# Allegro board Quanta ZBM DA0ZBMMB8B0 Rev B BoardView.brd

Outline 198.2 x 89.4 mm; copper layers: TOP, SGND, IN1, IN2, IN3, IN4, IN5, BOTTOM. Coordinates in mm from the lower left corner of the outline.
Outline path: 0,79.66 0,69.3 arc(0.59,67.89) 2,67.3 2.05,67.3 arc(2.4,67.15) 2.55,66.8 2.55,64.15 3.15,63.55 8.85,63.55 arc(9.35,64.05) 9.85,63.55 9.85,50.05 arc(9.35,49.55) 8.85,50.05 3.55,50.05 2.95,49.45 2.95,48.25 arc(3.29,47.57) 2.7,47.1 2.2,47.1 arc(1.85,46.95) 1.7,46.6 1.7,45.65 2.3,45.05 12.41,45.05 arc(12.91,44.55) 12.41,44.05 12.41,38.5 arc(12.91,38) 12.41,37.5 1.85,37.5 1.25,36.9 1.25,35.1 2.7,35.1 arc(3.2,34.6) 2.7,34.1 1.25,34.1 1.25,18.6 arc(1.4,18.25) 1.75,18.1 3.75,18.1 arc(4.1,17.95) 4.25,17.6 4.25,15.3 arc(4.1,14.95) 3.75,14.8 1.75,14.8 arc(1.4,14.65) 1.25,14.3 1.25,2.4 arc(1.4,2.05) 1.75,1.9 2.35,1.9 arc(2.7,1.75) 2.85,1.4 2.85,1 arc(3.14,0.29) 3.85,0 7.35,0 arc(7.97,0.22) 8.32,0.79 9.56,6.46 arc(9.74,6.74) 10.05,6.85 21.45,6.85 arc(21.8,6.7) 21.95,6.35 21.95,6.1 arc(22.1,5.75) 22.45,5.6 78.2,5.6 arc(80.32,6.48) 81.2,8.6 arc(81.49,9.31) 82.2,9.6 197.2,9.6 arc(197.91,9.89) 198.2,10.6 198.2,88.4 arc(197.91,89.11) 197.2,89.4 79.17,89.4 arc(78.75,89.3) 78.4,89.03 68.42,76.87 arc(68.26,76.6) 68.2,76.29 arc(67.58,74.95) 66.2,74.4 36.7,74.4 arc(36.35,74.25) 36.2,73.9 arc(36.05,73.55) 35.7,73.4 18.8,73.4 18.8,73.6 arc(18.51,74.31) 17.8,74.6 14.8,74.6 arc(14.09,74.89) 13.8,75.6 13.8,76.66 arc(12.34,80.2) 8.8,81.66 2,81.66 arc(0.59,81.07) 0,79.66

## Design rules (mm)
constraint set DEFAULT: min track width 0.109
net group DFP-S3.5(3.2: nets M_A_DQS_0_DN M_A_DQS_0_DP M_A_DQS_1_DN M_A_DQS_1_DP M_A_DQS_2_DN M_A_DQS_2_DP M_A_DQS_3_DN M_A_DQS_3_DP M_A_LP4_CLK_DN M_A_LP4_CLK_DP M_B_DQS_0_DN M_B_DQS_0_DP M_B_DQS_1_DN M_B_DQS_1_DP M_B_DQS_2_DN M_B_DQS_2_DP M_B_DQS_3_DN M_B_DQS_3_DP M_B_LP4_CLK_DN M_B_LP4_CLK_DP M_C_DQS_0_DN M_C_DQS_0_DP M_C_DQS_1_DN M_C_DQS_1_DP M_C_DQS_2_DN M_C_DQS_2_DP M_C_DQS_3_DN M_C_DQS_3_DP M_C_LP4_CLK_DN M_C_LP4_CLK_DP M_D_DQS_0_DN M_D_DQS_0_DP M_D_DQS_1_DN M_D_DQS_1_DP M_D_DQS_2_DN M_D_DQS_2_DP M_D_DQS_3_DN M_D_DQS_3_DP M_D_LP4_CLK_DN M_D_LP4_CLK_DP
net group DFP-S3.5(4.2: nets CNV_CLK_PCH_RX_WLAN_TX_N CNV_CLK_PCH_RX_WLAN_TX_P CNV_CLK_PCH_TX_WLAN_RX_N CNV_CLK_PCH_TX_WLAN_RX_P CNV_D0_PCH_RX_WLAN_TX_N CNV_D0_PCH_RX_WLAN_TX_P CNV_D0_PCH_TX_WLAN_RX_N CNV_D0_PCH_TX_WLAN_RX_P CNV_D1_PCH_RX_WLAN_TX_N CNV_D1_PCH_RX_WLAN_TX_P CNV_D1_PCH_TX_WLAN_RX_N CNV_D1_PCH_TX_WLAN_RX_P EDP_AUX_C_N EDP_AUX_C_P EDP_AUX_N EDP_AUX_P EDP_TX0_C_N EDP_TX0_C_P EDP_TX0_N EDP_TX0_P EDP_TX1_C_N EDP_TX1_C_P EDP_TX1_N EDP_TX1_P EDP_TX2_C_N EDP_TX2_C_P EDP_TX2_N EDP_TX2_P EDP_TX3_C_N EDP_TX3_C_P EDP_TX3_N EDP_TX3_P H1_SBU1 H1_SBU2 N18155934 N18155937 N18182049 N18182083 PCIE_4_PCH_RX_WLAN_TX_C_N PCIE_4_PCH_RX_WLAN_TX_C_P PCIE_4_PCH_RX_WLAN_TX_N PCIE_4_PCH_RX_WLAN_TX_P PCIE_4_PCH_TX_WLAN_RX_C_N PCIE_4_PCH_TX_WLAN_RX_C_P PCIE_4_PCH_TX_WLAN_RX_N PCIE_4_PCH_TX_WLAN_RX_P PCIE_4_WLAN_REFCLK_N PCIE_4_WLAN_REFCLK_P PCIE_SUB_REFCLK_N PCIE_SUB_REFCLK_P USB2_BT_N USB2_BT_P USB2_UFC_N USB2_UFC_P USB_A0_SSRX_L_N USB_A0_SSRX_L_P USB_A0_SSRX_N USB_A0_SSRX_P USB_A0_SSTX_C_N USB_A0_SSTX_C_P USB_A0_SSTX_L_N USB_A0_SSTX_L_P USB_A0_SSTX_N USB_A0_SSTX_P USB_A0_USB2_L_N USB_A0_USB2_L_P USB_A0_USB2_N USB_A0_USB2_P USB_A0_USB2_U_N USB_A0_USB2_U_P USB_A1_SSRX_N USB_A1_SSRX_P USB_A1_SSTX_N USB_A1_SSTX_P USB_A1_USB2_N USB_A1_USB2_P USB_C0_AUX_DC_N USB_C0_AUX_DC_P USB_C0_AUX_N USB_C0_AUX_P USB_C0_ML0_N USB_C0_ML0_P USB_C0_ML1_N USB_C0_ML1_P USB_C0_ML2_N USB_C0_ML2_P USB_C0_ML3_N USB_C0_ML3_P USB_C0_RX1_C_N USB_C0_RX1_C_P USB_C0_RX1_L_N USB_C0_RX1_L_P USB_C0_RX1_U_N USB_C0_RX1_U_P USB_C0_RX2_C_N USB_C0_RX2_C_P USB_C0_RX2_L_N USB_C0_RX2_L_P USB_C0_RX2_U_N USB_C0_RX2_U_P USB_C0_SBU1_C USB_C0_SBU1_U USB_C0_SBU2_C USB_C0_SBU2_U USB_C0_SSRX_N USB_C0_SSRX_P USB_C0_SSTX_N USB_C0_SSTX_P USB_C0_TX1_C_N USB_C0_TX1_C_P USB_C0_TX1_L_N USB_C0_TX1_L_P USB_C0_TX1_U_N USB_C0_TX1_U_P USB_C0_TX2_C_N USB_C0_TX2_C_P USB_C0_TX2_L_N USB_C0_TX2_L_P USB_C0_TX2_U_N USB_C0_TX2_U_P USB_C0_USB2_L_N USB_C0_USB2_L_P USB_C0_USB2_N USB_C0_USB2_P USB_C0_USB2_U_N USB_C0_USB2_U_P USB_C1_AUX_N USB_C1_AUX_P USB_C1_ML0_N USB_C1_ML0_P USB_C1_ML1_N USB_C1_ML1_P USB_C1_ML2_N USB_C1_ML2_P USB_C1_ML3_N USB_C1_ML3_P USB_C1_SSRX_N USB_C1_SSRX_P USB_C1_SSTX_N USB_C1_SSTX_P USB_C1_USB2_N USB_C1_USB2_P
net group DFP-S4W4.3(3.8: nets PPVAR_VCC_IN_SNS_N PPVAR_VCC_IN_SNS_P VCCIN_AUX_SENSE_N VCCIN_AUX_SENSE_P
net group DFP-S7.2(6: nets HDMI_DDC_SCL HDMI_DDC_SDA USB_C1_AUX_N_HDMI_DDC_SDA USB_C1_AUX_P_HDMI_DDC_SCL
net group DFP-S7W4.3(3.8: nets AP_I2C_AUDIO_SCL AP_I2C_AUDIO_SDA AP_I2C_CAM_SCL AP_I2C_CAM_SDA AP_I2C_EMR_SCL AP_I2C_EMR_SDA AP_I2C_SUB_SCL AP_I2C_SUB_SDA AP_I2C_TRACKPAD_SCL_3V3 AP_I2C_TRACKPAD_SDA_3V3 AP_I2C_TS_SCL AP_I2C_TS_SDA DEBUG_I2C_INA_SCL DEBUG_I2C_INA_SDA EC_I2C_BATTERY_SCL EC_I2C_BATTERY_SDA EC_I2C_EEPROM_SCL EC_I2C_EEPROM_SDA EC_I2C_SENSOR_SCL EC_I2C_SENSOR_SDA EC_I2C_SUB_USB_C1_SCL EC_I2C_SUB_USB_C1_SDA EC_I2C_USB_C0_SCL EC_I2C_USB_C0_SDA N17997033 N17997051 N17999580 N17999587 N18002909 N18002922
net group GND: nets GND
net group W3.5-T124B: nets IBAT_N IBAT_P USB_C0_IBUS_N USB_C0_IBUS_P
net group W3.8-T124B: nets HP_RING2_SENSE
net group W4.3(3.8: nets AP_SPI_FLASH_CLK AP_SPI_FLASH_CLK_R AP_SPI_FLASH_CS_L AP_SPI_FLASH_CS_L_R AP_SPI_FLASH_MISO AP_SPI_FLASH_MISO_R AP_SPI_FLASH_MOSI AP_SPI_FLASH_MOSI_R AP_SPI_H1_TPM_CLK AP_SPI_H1_TPM_CLK_R AP_SPI_H1_TPM_CS_L AP_SPI_H1_TPM_MISO AP_SPI_H1_TPM_MISO_R AP_SPI_H1_TPM_MOSI AP_SPI_H1_TPM_MOSI_R CLK_24M_UCAM CLK_24M_WCAM CLK_BIASREF CNV_BRI_DT CNV_BRI_RSP CNV_CLKREQ0 CNV_RGI_DT CNV_RGI_RSP DMIC0_CLK DMIC0_CLK_R DMIC0_DATA DMIC0_DATA_R DMIC1_CLK_R DMIC1_DATA EMMC_CLK EMMC_CMD EMMC_D0 EMMC_D0_R EMMC_D1 EMMC_D1_R EMMC_D2 EMMC_D2_R EMMC_D3 EMMC_D3_R EMMC_D4 EMMC_D4_R EMMC_D5 EMMC_D5_R EMMC_D6 EMMC_D6_R EMMC_D7 EMMC_D7_R EMMC_RCLK EMMC_RCOMP EMMC_RST_L ESPI_CLK ESPI_CLK_R ESPI_IO0 ESPI_IO0_R ESPI_IO1 ESPI_IO1_R ESPI_IO2 ESPI_IO2_R ESPI_IO3 ESPI_IO3_R GPPC_E_6_IMGCLKOUT_3 GPPC_E_12_IMGCLKOUT_4 H1_SPI_CLK H1_SPI_CS_L H1_SPI_MISO H1_SPI_MOSI HP_MIC_N HP_MIC_P I2S_HP_AUDIO I2S_HP_BCLK I2S_HP_LRCK I2S_HP_MIC I2S_MCLK I2S_SPK_AUDIO I2S_SPK_BCLK I2S_SPK_LRCK IMVP9_SVID_ALERT_ODL IMVP9_SVID_CLK IMVP9_SVID_DATA N17801684 N17801691 N17813996 N17814026 N17814069 N17814071 N17814073 N17814084 SD_CLK SD_CMD SD_CMD_R SD_DATA0 SD_DATA0_R SD_DATA1 SD_DATA1_R SD_DATA2 SD_DATA2_R SD_DATA3 SD_DATA3_R WLAN_SUSCLK WLAN_SUSCLK_R XTAL_PCH_38P4M_IN XTAL_PCH_38P4M_OUT XTAL_RTC_32K_IN XTAL_RTC_32K_OUT
net group W4.3-T124B: nets HP_SLEEVE_SENSE
net group W6.8(5.3: nets M_A_DQ_0_0 M_A_DQ_0_1 M_A_DQ_0_2 M_A_DQ_0_3 M_A_DQ_0_4 M_A_DQ_0_5 M_A_DQ_0_6 M_A_DQ_0_7 M_A_DQ_1_0 M_A_DQ_1_1 M_A_DQ_1_2 M_A_DQ_1_3 M_A_DQ_1_4 M_A_DQ_1_5 M_A_DQ_1_6 M_A_DQ_1_7 M_A_DQ_2_0 M_A_DQ_2_1 M_A_DQ_2_2 M_A_DQ_2_3 M_A_DQ_2_4 M_A_DQ_2_5 M_A_DQ_2_6 M_A_DQ_2_7 M_A_DQ_3_0 M_A_DQ_3_1 M_A_DQ_3_2 M_A_DQ_3_3 M_A_DQ_3_4 M_A_DQ_3_5 M_A_DQ_3_6 M_A_DQ_3_7 M_A_LP4_CA0 M_A_LP4_CA1 M_A_LP4_CA2 M_A_LP4_CA3 M_A_LP4_CA4 M_A_LP4_CA5 M_A_LP4_CKE0_N M_A_LP4_CKE1_N M_A_LP4_CS0_N M_A_LP4_CS1_N M_B_DQ_0_0 M_B_DQ_0_1 M_B_DQ_0_2 M_B_DQ_0_3 M_B_DQ_0_4 M_B_DQ_0_5 M_B_DQ_0_6 M_B_DQ_0_7 M_B_DQ_1_0 M_B_DQ_1_1 M_B_DQ_1_2 M_B_DQ_1_3 M_B_DQ_1_4 M_B_DQ_1_5 M_B_DQ_1_6 M_B_DQ_1_7 M_B_DQ_2_0 M_B_DQ_2_1 M_B_DQ_2_2 M_B_DQ_2_3 M_B_DQ_2_4 M_B_DQ_2_5 M_B_DQ_2_6 M_B_DQ_2_7 M_B_DQ_3_0 M_B_DQ_3_1 M_B_DQ_3_2 M_B_DQ_3_3 M_B_DQ_3_4 M_B_DQ_3_5 M_B_DQ_3_6 M_B_DQ_3_7 M_B_LP4_CA0 M_B_LP4_CA1 M_B_LP4_CA2 M_B_LP4_CA3 M_B_LP4_CA4 M_B_LP4_CA5 M_B_LP4_CKE0_N M_B_LP4_CKE1_N M_B_LP4_CS0_N M_B_LP4_CS1_N M_C_DQ_0_0 M_C_DQ_0_1 M_C_DQ_0_2 M_C_DQ_0_3 M_C_DQ_0_4 M_C_DQ_0_5 M_C_DQ_0_6 M_C_DQ_0_7 M_C_DQ_1_0 M_C_DQ_1_1 M_C_DQ_1_2 M_C_DQ_1_3 M_C_DQ_1_4 M_C_DQ_1_5 M_C_DQ_1_6 M_C_DQ_1_7 M_C_DQ_2_0 M_C_DQ_2_1 M_C_DQ_2_2 M_C_DQ_2_3 M_C_DQ_2_4 M_C_DQ_2_5 M_C_DQ_2_6 M_C_DQ_2_7 M_C_DQ_3_0 M_C_DQ_3_1 M_C_DQ_3_2 M_C_DQ_3_3 M_C_DQ_3_4 M_C_DQ_3_5 M_C_DQ_3_6 M_C_DQ_3_7 M_C_LP4_CA0 M_C_LP4_CA1 M_C_LP4_CA2 M_C_LP4_CA3 M_C_LP4_CA4 M_C_LP4_CA5 M_C_LP4_CKE0_N M_C_LP4_CKE1_N M_C_LP4_CS0_N M_C_LP4_CS1_N M_D_DQ_0_0 M_D_DQ_0_1 M_D_DQ_0_2 M_D_DQ_0_3 M_D_DQ_0_4 M_D_DQ_0_5 M_D_DQ_0_6 M_D_DQ_0_7 M_D_DQ_1_0 M_D_DQ_1_1 M_D_DQ_1_2 M_D_DQ_1_3 M_D_DQ_1_4 M_D_DQ_1_5 M_D_DQ_1_6 M_D_DQ_1_7 M_D_DQ_2_0 M_D_DQ_2_1 M_D_DQ_2_2 M_D_DQ_2_3 M_D_DQ_2_4 M_D_DQ_2_5 M_D_DQ_2_6 M_D_DQ_2_7 M_D_DQ_3_0 M_D_DQ_3_1 M_D_DQ_3_2 M_D_DQ_3_3 M_D_DQ_3_4 M_D_DQ_3_5 M_D_DQ_3_6 M_D_DQ_3_7 M_D_LP4_CA0 M_D_LP4_CA1 M_D_LP4_CA2 M_D_LP4_CA3 M_D_LP4_CA4 M_D_LP4_CA5 M_D_LP4_CKE0_N M_D_LP4_CKE1_N M_D_LP4_CS0_N M_D_LP4_CS1_N
net group W10-T12345B: nets PP3300_TOUCH_S0
net group W15-T124B: nets PP3300_AP_FLASH
net group W20-T124B: nets H1_CC1 H1_CC2 HP_GND_RING2 HP_GND_SLEEVE HP_LEFT HP_RIGHT HP_RING1 HP_TIP N18000635 PP1800_HP_IO PP1800_LSPK_A PP1800_RSPK_A PP1800A_HP PP3300_HP_MIC PP5000_LSPK_U PP5000_RSPK_U PP5000_U USB_C0_CC1 USB_C0_CC1_C USB_C0_CC2 USB_C0_CC2_C
net group W20-T1234B: nets PP3300_G
net group W30-T124B: nets LSPK_N LSPK_P LSPK_R_N LSPK_R_P RSPK_N RSPK_P RSPK_R_N RSPK_R_P

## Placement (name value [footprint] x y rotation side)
C1  8.2p/50V_4  [C0402]  124.68 65.3 0 bottom
C1A6  1u/10V_2  [C0201-SMT-TEST]  84.28 14.5 90 top
C2  8.2p/50V_4  [C0402]  133.19 63.27 90 bottom
C3  8.2p/50V_4  [C0402]  135.47 64.03 90 bottom
C3C8  1u/25V_4  [C0402]  87.97 40.03 90 top
C3C9  1u/25V_4  [C0402]  87.97 43.33 270 top
C4  *15p/25V_2  [C0201-SMT-TEST]  137 68.73 90 top
C5  *15p/25V_2  [C0201-SMT-TEST]  137.76 68.73 90 top
C6  *15p/25V_2  [C0201-SMT-TEST]  136.87 64.03 270 top
C7  *15p/25V_2  [C0201-SMT-TEST]  137.63 64.03 270 top
C8  *1u/10V_2  [C0201-SMT-TEST]  133.31 64.8 0 bottom
C9  *1u/10V_2  [C0201-SMT-TEST]  125.95 68.86 0 bottom
C10  15p/25V_2  [C0201-SMT-TEST]  94.96 41.56 270 top
C11  1u/10V_2  [C0201-SMT-TEST]  115.97 77.15 180 top
C12  *0.1u/16V_2  [C0201-SMT-TEST]  106.77 60.12 270 bottom
C13  *1u/10V_2  [C0201-SMT-TEST]  106.77 58.45 270 bottom
C14  15p/25V_2  [C0201-SMT-TEST]  119.95 44.48 90 top
C15  4.7u/10V_4  [C0402_2]  122.26 57.3 180 bottom
C16  10u/6.3V_4  [C0402_2]  125.06 59.34 90 bottom
C17  3p/50V_2  [C0201-SMT-TEST]  95.72 41.56 270 top
C18  *0.1u/16V_2  [C0201-SMT-TEST]  71.01 64.45 315 bottom
C19  *0.1u/16V_2  [C0201-SMT-TEST]  69.87 63.31 315 bottom
C20  4.7u/6.3V_4  [C0402_2]  173.91 21.36 90 bottom
C21  1u/6.3V_2  [C0201-SMT-TEST]  163.62 30.61 90 top
C22  3p/50V_2  [C0201-SMT-TEST]  120.71 44.48 90 top
C23  15p/25V_2  [C0201-SMT-TEST]  145.43 52.34 90 top
C24  15p/25V_2  [C0201-SMT-TEST]  107.66 44.86 180 top
C25  3p/50V_2  [C0201-SMT-TEST]  146.2 52.34 90 top
C26  3p/50V_2  [C0201-SMT-TEST]  107.66 44.1 180 top
C27  15p/25V_2  [C0201-SMT-TEST]  133.37 46.5 180 top
C28  3p/50V_2  [C0201-SMT-TEST]  133.37 45.73 180 top
C29  1u/10V_2  [C0201-SMT-TEST]  114.57 76.39 180 top
C30  15p/50V_2  [C0201-SMT-TEST]  127.98 25.93 180 top
C31  15p/50V_2  [C0201-SMT-TEST]  158.9 31.18 270 top
C32  *12p/50V_4  [C0402]  92.47 76.63 90 bottom
C33  3p/50V_2  [C0201-SMT-TEST]  101.94 27.2 270 top
C34  3p/50V_2  [C0201-SMT-TEST]  159.66 31.18 270 top
C35  15p/50V_2  [C0201-SMT-TEST]  127.98 25.17 180 top
C36  15p/50V_2  [C0201-SMT-TEST]  102.71 27.2 270 top
C37  3p/50V_2  [C0201-SMT-TEST]  144.23 29.24 315 top
C38  3p/50V_2  [C0201-SMT-TEST]  146.01 29.74 315 top
C39  15p/50V_2  [C0201-SMT-TEST]  160.88 44.72 0 top
C40  3p/50V_2  [C0201-SMT-TEST]  160.88 43.9 0 top
C41  8.2p/50V_4  [C0402]  115.61 66.7 180 bottom
C42  8.2p/50V_4  [C0402]  115.68 68.86 0 bottom
C43  8.2p/50V_4  [C0402]  113.12 69.22 90 bottom
C44  8.2p/50V_4  [C0402]  108.17 66.35 90 bottom
C45  8.2p/50V_4  [C0402]  91.48 76.64 90 bottom
C46  8.2p/50V_4  [C0402]  106.82 66.35 90 bottom
C47  47u/6.3V_6  [C0603]  122.83 62.42 90 bottom
C48  *1u/10V_2  [C0201-SMT-TEST]  103.72 52.6 0 bottom
C49  10u/10V_6  [C0603]  149.5 30.8 180 top
C50  0.1u/10V_2  [C0201-SMT-TEST]  167.21 20.37 180 bottom
C51  0.1u/10V_2  [C0201-SMT-TEST]  165.22 25.18 90 top
C52  0.1u/10V_2  [C0201-SMT-TEST]  161.23 23.08 180 top
C53  0.1u/10V_2  [C0201-SMT-TEST]  167.21 19.2 180 bottom
C54  *0.1u/6.3V_2  [C0201-SMT-TEST]  113.88 57.3 180 bottom
C55  *0.1u/6.3V_2  [C0201-SMT-TEST]  115.91 59.72 90 bottom
C56  *22u/6.3V_6  [C0603]  141.82 60.22 0 top
C57  *0.1u/6.3V_2  [C0201-SMT-TEST]  115.15 58.32 0 bottom
C58  1u/10V_4  [C0402]  126.71 65.69 0 bottom
C59  1u/10V_4  [C0402]  125.44 63.78 0 bottom
C60  0.1u/10V_2  [C0201-SMT-TEST]  162.78 24.62 90 bottom
C61  4.7u/10V_4  [C0402_2]  167.77 17.91 180 bottom
C62  0.1u/10V_2  [C0201-SMT-TEST]  165.93 16.95 270 top
C63  2.2u/6.3V_2  [C0201-SMT-TEST]  73.5 44.48 0 top
C64  4.7u/10V_4  [C0402_2]  64.79 47.31 270 bottom
C65  4.7u/10V_4  [C0402_2]  69.81 50.06 90 bottom
C66  0.1u/10V_2  [C0201-SMT-TEST]  67.58 44.64 270 bottom
C67  0.1u/10V_2  [C0201-SMT-TEST]  66.06 44 180 bottom
C68  1u/16V_4  [C0402]  24.15 45.02 270 top
C69  2.2u/10V_4  [C0402]  17.67 43.88 270 top
C70  2.2u/10V_4  [C0402]  19.58 33.72 90 top
C71  2.2u/6.3V_4  [C0402]  16.78 34.35 90 top
C72  2.2u/6.3V_4  [C0402]  24.55 42 270 top
C73  2.2u/10V_4  [C0402]  17.29 38.16 90 bottom
C74  0.1u/16V_2  [C0201-SMT-TEST]  17.16 35.62 0 top
C75  0.1u/16V_2  [C0201-SMT-TEST]  23.71 42 270 top
C76  2.2u/10V_4  [C0402]  15.89 42.23 270 top
C77  2.2u/6.3V_4  [C0402]  16.27 44.77 0 top
C78  1u/16V_4  [C0402]  23.61 34.1 90 top
C79  4.7u/6.3V_4  [C0402_2]  21.46 45.34 0 top
C80  1u/16V_4  [C0402]  20.85 33.72 90 top
C81  0.1u/16V_2  [C0201-SMT-TEST]  16.4 43.62 0 top
C82  2.2u/10V_4  [C0402]  18.18 33.21 180 top
C83  2.2u/10V_4  [C0402]  18.18 34.22 0 top
C84  1u/16V_4  [C0402]  20.06 43.88 270 top
C85  1u/16V_4  [C0402]  21.1 43.88 270 top
C89  GS@0.1u/10V_2  [C0201-SMT-TEST]  170.07 70.42 0 bottom
C90  GS@0.1u/10V_2  [C0201-SMT-TEST]  168.29 75.25 0 bottom
C92  GS@1u/6.3V_2  [C0201-SMT-TEST]  169.06 70.42 180 bottom
C96  TS@1u/6.3V_2  [C0201-SMT-TEST]  30.75 48.83 180 top
C98  22u/6.3V_6  [C0603]  20.34 56.83 0 top
C102  0.1u/16V_2  [C0201-SMT-TEST]  36.3 26.61 90 bottom
C103  10u/10V_4  [C0402_2]  33.17 10.35 180 top
C104  *10u/10V_4  [C0402_2]  42.51 13.24 0 top
C105  0.1u/16V_2  [C0201-SMT-TEST]  33.17 12.38 180 top
C106  *0.1u/16V_2  [C0201-SMT-TEST]  42.52 15.23 0 top
C107  0.01u/16V_4  [C0402]  33.17 11.49 180 top
C108  *0.01u/16V_4  [C0402]  42.51 14.34 0 top
C109  *0.1u/16V_2  [C0201-SMT-TEST]  39.2 25.72 270 bottom
C110  *0.1u/16V_2  [C0201-SMT-TEST]  39.96 25.72 270 bottom
C111  0.1u/6.3V_2  [C0201-SMT-TEST]  150.01 24.78 90 bottom
C112  1u/6.3V_4  [C0402]  144.04 24.78 0 top
C113  0.1u/6.3V_2  [C0201-SMT-TEST]  154.53 27.57 180 bottom
C114  0.1u/6.3V_2  [C0201-SMT-TEST]  150.72 17.56 180 top
C115  0.1u/6.3V_2  [C0201-SMT-TEST]  157.07 26.11 270 bottom
C116  0.1u/6.3V_2  [C0201-SMT-TEST]  154.58 17.59 0 top
C117  0.1u/6.3V_2  [C0201-SMT-TEST]  149.29 23.73 270 bottom
C118  4.7u/10V_4  [C0402_2]  150.56 16.61 0 top
C119  0.1u/6.3V_2  [C0201-SMT-TEST]  156.11 20.93 270 bottom
C120  0.1u/6.3V_2  [C0201-SMT-TEST]  155.11 16.83 0 top
C121  0.1u/6.3V_2  [C0201-SMT-TEST]  152.29 27.55 0 bottom
C122  4.7u/10V_4  [C0402_2]  155.49 15.68 180 top
C123  0.1u/6.3V_2  [C0201-SMT-TEST]  154.45 18.68 90 bottom
C124  10u/6.3V_4  [C0402_2]  155.85 27.57 90 bottom
C125  22u/25V_8  [C0805]  167.4 66.86 0 top
C126  22u/25V_8  [C0805]  170.1 72.25 270 top
C127  0.1u/6.3V_2  [C0201-SMT-TEST]  153.69 21.91 270 bottom
C128  0.1u/6.3V_2  [C0201-SMT-TEST]  155.59 17.59 180 top
C129  0.1u/10V_2  [C0201-SMT-TEST]  162.45 17.16 180 top
C130  UR@0.1u/16V_2  [C0201-SMT-TEST]  174.71 29.24 180 top
C131  22u/25V_8  [C0805]  23.13 27.24 180 top
C132  0.1u/16V_2  [C0201-SMT-TEST]  24.1 20.79 180 top
C133  1u/6.3V_2  [C0201-SMT-TEST]  24.1 22.31 0 top
C134  1u/6.3V_2  [C0201-SMT-TEST]  24.1 21.6 0 top
C135  0.1u/16V_2  [C0201-SMT-TEST]  23.73 25.87 180 top
C136  0.1u/16V_2  [C0201-SMT-TEST]  21.16 18.48 180 top
C137  0.22u/10V_2  [C0201-SMT-TEST]  20.14 26.87 0 top
C138  0.22u/10V_2  [C0201-SMT-TEST]  24.23 23.18 90 top
C139  22u/25V_8  [C0805]  27.1 17.9 0 top
C140  0.1u/16V_2  [C0201-SMT-TEST]  28.82 10.91 180 top
C141  1u/6.3V_2  [C0201-SMT-TEST]  28.82 12.43 0 top
C142  1u/6.3V_2  [C0201-SMT-TEST]  28.82 11.67 0 top
C143  0.1u/16V_2  [C0201-SMT-TEST]  27.25 16.55 0 top
C144  0.1u/16V_2  [C0201-SMT-TEST]  24.2 9.08 90 top
C145  0.22u/10V_2  [C0201-SMT-TEST]  24.43 17.21 0 top
C146  0.22u/10V_2  [C0201-SMT-TEST]  28.16 13.4 90 top
C148  1u/10V_2  [C0201-SMT-TEST]  159.99 25.08 90 bottom
C149  0.1u/25V_2  [C0201-SMT-TEST]  42.6 59.88 90 bottom
C150  0.1u/25V_2  [C0201-SMT-TEST]  43.36 59.88 90 bottom
C151  0.1u/25V_2  [C0201-SMT-TEST]  48.53 64.58 270 top
C152  0.1u/25V_2  [C0201-SMT-TEST]  49.29 64.58 270 top
C153  0.1u/25V_2  [C0201-SMT-TEST]  50.18 64.83 270 top
C154  0.1u/25V_2  [C0201-SMT-TEST]  50.95 64.83 270 top
C155  10u/6.3V_4  [C0402_2]  156.98 23.68 270 bottom
C156  0.22u/6.3V_2  [C0201-SMT-TEST]  18.05 55.94 180 top
C157  0.22u/6.3V_2  [C0201-SMT-TEST]  18.05 55.18 180 top
C158  4.7u/6.3V_4  [C0402_2]  15.71 26.67 90 top
C159  0.1u/25V_2  [C0201-SMT-TEST]  14.75 26.02 270 top
C160  150u/6.3V_3528H1.9  [C3528]  15.73 61.3 90 top
C161  0.1u/25V_2  [C0201-SMT-TEST]  31.26 67.73 270 top
C162  0.1u/25V_2  [C0201-SMT-TEST]  30.5 67.73 270 top
C163  0.1u/6.3V_2  [C0201-SMT-TEST]  32.91 65.59 180 bottom
C164  10u/6.3V_4  [C0402_2]  30.65 66.32 0 bottom
C165  0.1u/6.3V_2  [C0201-SMT-TEST]  30.24 60.07 180 bottom
C166  1u/6.3V_2  [C0201-SMT-TEST]  30.24 59.33 180 bottom
C167  1u/6.3V_2  [C0201-SMT-TEST]  30.24 60.84 180 bottom
C168  0.33u/25V_2  [C0201-SMT-TEST]  8.72 68.73 90 bottom
C169  0.33u/25V_2  [C0201-SMT-TEST]  9.43 68.73 90 bottom
C170  0.1u/25V_2  [C0201-SMT-TEST]  10.58 75.15 90 top
C171  0.1u/25V_2  [C0201-SMT-TEST]  11.3 75.15 90 top
C172  0.33u/25V_2  [C0201-SMT-TEST]  9.26 71.23 180 top
C173  0.33u/25V_2  [C0201-SMT-TEST]  9.26 70.47 180 top
C174  2.2u/6.3V_2  [C0201-SMT-TEST]  111.02 66.23 270 bottom
C175  0.1u/25V_2  [C0201-SMT-TEST]  8.17 67.84 135 bottom
C176  0.1u/25V_2  [C0201-SMT-TEST]  7.6 67.27 135 bottom
C177  0.1u/50V_4  [C0402]  35.22 68.03 0 top
C178  0.1u/10V_2  [C0201-SMT-TEST]  129.38 66.57 0 bottom
C179  *1u/10V_2  [C0201-SMT-TEST]  131.74 68.35 90 bottom
C180  4.7u/10V_4  [C0402_2]  133.19 66.45 180 bottom
C181  0.1u/50V_4  [C0402]  9.17 72.62 180 top
C182  10u/25V_8  [C0805]  49.57 11.51 180 bottom
C183  22u/25V_8  [C0805]  56.79 13.59 180 top
C184  0.1u/10V_2  [C0201-SMT-TEST]  128.23 66.57 0 bottom
C185  *1u/10V_2  [C0201-SMT-TEST]  127.19 62.89 270 bottom
C186  4.7u/10V_4  [C0402_2]  131.81 63.27 90 bottom
C187  4.7u/6.3V_4  [C0402_2]  66.55 17.08 180 top
C188  22u/25V_8  [C0805]  56.05 8.65 180 top
C189  4.7u/25V_6  [C0603]  62.5 15.84 0 bottom
C190  0.1u/25V_4  [C0402]  131.41 64.8 180 bottom
C191  4.7u/10V_4  [C0402_2]  125.44 66.83 0 bottom
C192  22u/25V_8  [C0805]  56.79 11.61 180 top
C193  22u/25V_8  [C0805]  56.66 15.58 180 top
C194  0.1u/25V_4  [C0402]  57.04 10.14 180 top
C195  0.1u/25V_4  [C0402]  127.14 64.34 90 bottom
C196  4.7u/10V_4  [C0402_2]  133.44 68.1 0 bottom
C197  0.47u/50V_6  [C0603]  55.6 18.6 90 top
C198  0.47u/50V_6  [C0603]  60.66 23.75 180 top
C199  0.1u/25V_4  [C0402]  47.52 33.72 0 top
C200  4.7u/10V_4  [C0402_2]  66.57 17.08 180 bottom
C201  22u/25V_8  [C0805]  60.57 29.78 270 top
C202  4.7u/10V_4  [C0402_2]  57.55 21.65 0 top
C203  22u/25V_8  [C0805]  178.39 75.86 90 top
C204  22u/25V_8  [C0805]  53.36 32.45 270 top
C205  *1u/10V_2  [C0201-SMT-TEST]  110.51 63.69 180 bottom
C206  *1u/10V_2  [C0201-SMT-TEST]  113.12 66.8 90 bottom
C207  2.2u/6.3V_2  [C0201-SMT-TEST]  116.17 64.68 90 bottom
C208  *1u/10V_2  [C0201-SMT-TEST]  109.49 66.23 270 bottom
C209  2.2u/6.3V_2  [C0201-SMT-TEST]  111.14 65.21 180 bottom
C210  *1u/10V_2  [C0201-SMT-TEST]  115.97 67.83 180 bottom
C211  2.2u/6.3V_2  [C0201-SMT-TEST]  110.51 64.45 180 bottom
C212  4.7u/25V_6  [C0603]  60.34 16.57 270 bottom
C213  22u/25V_8  [C0805]  55.34 32.45 270 top
C214  22u/25V_8  [C0805]  57.32 32.45 270 top
C215  22u/25V_8  [C0805]  62.55 29.81 270 top
C216  22u/25V_8  [C0805]  48.24 30.16 0 top
C217  22u/25V_8  [C0805]  176.38 75.86 90 top
C218  22u/25V_8  [C0805]  64.53 29.81 270 top
C219  22u/25V_8  [C0805]  48.28 32.19 0 top
C220  22u/25V_8  [C0805]  56.99 43.84 90 top
C221  22u/25V_8  [C0805]  52.92 43.84 90 top
C222  22u/25V_8  [C0805]  58.96 43.84 90 top
C223  22u/25V_8  [C0805]  53.64 51.37 270 top
C224  22u/25V_8  [C0805]  54.95 43.84 90 top
C226  22u/25V_8  [C0805]  173.04 33.16 0 top
C227  22u/25V_8  [C0805]  173.05 35.21 0 top
C230  0.22u/25V_4  [C0402]  178.27 58.07 270 top
C231  2.2u/10V_4  [C0402]  176.24 51.46 90 top
C232  0.47u/25V_4  [C0402]  181.76 54.42 180 bottom
C233  10u/10V_4  [C0402_2]  178.4 37.11 90 top
C234  0.1u/25V_4  [C0402]  174.33 54.18 270 top
C235  22u/25V_8  [C0805]  166.21 34.7 90 top
C236  22u/25V_8  [C0805]  164.17 34.7 90 top
C237  22u/25V_8  [C0805]  162.14 34.7 90 top
C238  22u/25V_8  [C0805]  168.24 34.7 90 top
C239  4.7u/10V_4  [C0402_2]  82.06 54.67 180 top
C240  4.7u/10V_4  [C0402_2]  35.22 51.75 180 top
C241  4.7u/10V_4  [C0402_2]  87.59 38.25 270 top
C242  4.7u/10V_4  [C0402_2]  70.63 65.72 180 top
C243  *100p/25V_2  [C0201-SMT-TEST]  88.22 14.53 90 top
C244  10u/25V_6  [C0603]  85.62 15.58 0 bottom
C245  0.1u/50V_4  [C0402]  85.9 16.79 0 bottom
C248  1u/10V_4  [C0402]  40.43 45.65 270 top
C249  0.01u/16V_4  [C0402]  152.48 15.75 0 top
C250  22u/25V_8  [C0805]  43.62 33.25 90 top
C251  22u/25V_8  [C0805]  46.91 41.29 90 top
C252  *220p/25V_2  [C0201-SMT-TEST]  34.44 68.9 90 bottom
C253  22u/25V_8  [C0805]  42.94 41.29 90 top
C254  0.1u/25V_4  [C0402]  36.34 36.64 90 top
C255  0.1u/25V_4  [C0402]  34.51 46.64 90 top
C256  1u/10V_4  [C0402]  40.09 36.6 270 top
C257  10p/25V_2  [C0201-SMT-TEST]  38.32 47.15 0 top
C258  10p/25V_2  [C0201-SMT-TEST]  42.03 37.86 180 top
C259  22u/10V_8  [C0805]  29.05 43.22 0 top
C260  22u/10V_8  [C0805]  29.78 33.12 0 top
C261  22u/10V_8  [C0805]  29.05 41.19 0 top
C262  22u/10V_8  [C0805]  29.79 35.11 0 top
C263  *220p/25V_2  [C0201-SMT-TEST]  34.44 67.05 270 bottom
C264  0.1u/25V_2  [C0201-SMT-TEST]  39.77 63.12 90 top
C265  22u/25V_8  [C0805]  68.7 27.65 270 top
C266  0.1u/25V_4  [C0402]  79.65 26.22 0 top
C267  2.2u/10V_4  [C0402]  77.25 23.78 90 top
C268  22p/50V_2  [C0201-SMT-TEST]  74.51 23.23 90 top
C269  22u/10V_8  [C0805]  73.72 35.56 0 top
C270  22u/10V_8  [C0805]  73.72 31.49 0 top
C271  22u/10V_8  [C0805]  73.72 33.52 0 top
C272  4.7u/10V_4  [C0402_2]  16.77 30.19 0 top
C273  0.1u/25V_2  [C0201-SMT-TEST]  39.01 63.12 90 top
C274  0.1u/25V_2  [C0201-SMT-TEST]  37.74 63.12 90 top
C275  0.1u/25V_2  [C0201-SMT-TEST]  36.98 63.12 90 top
C276  47u/6.3V_8  [C0805]  150.33 68.25 270 top
C277  47u/6.3V_8  [C0805]  159.17 54.29 180 top
C278  47u/6.3V_8  [C0805]  152.36 67.72 270 top
C279  22u/25V_8  [C0805]  54.4 37.78 270 top
C280  10u/10V_4  [C0402_2]  56.48 39.14 0 top
C281  22u/25V_8  [C0805]  52.39 37.78 270 top
C282  0.1u/25V_2  [C0201-SMT-TEST]  55.77 37.27 90 top
C283  0.1u/25V_2  [C0201-SMT-TEST]  56.51 37.27 90 top
C284  0.1u/50V_4  [C0402]  62.83 35.71 90 top
C285  0.1u/50V_4  [C0402]  62.24 37.44 270 top
C286  22u/25V_8  [C0805]  69.64 31.94 90 top
C287  22u/25V_8  [C0805]  70.12 37.27 180 top
C288  22u/25V_8  [C0805]  67.66 31.94 90 top
C289  0.1u/25V_2  [C0201-SMT-TEST]  84.53 12.59 270 top
C290  100p/25V_2  [C0201-SMT-TEST]  41.29 44.98 270 top
C291  22u/6.3V_6  [C0603]  140.78 68.64 270 top
C292  22u/6.3V_6  [C0603]  141.82 58.78 0 top
C293  4.7u/10V_4  [C0402_2]  40.1 51.12 270 top
C294  1u/6.3V_2  [C0201-SMT-TEST]  177.92 30.21 90 top
C295  TS@4.7u/10V_4  [C0402_2]  35.22 50.56 180 top
C296  1000p/25V_2  [C0201-SMT-TEST]  37.43 54.51 90 top
C297  1000p/25V_2  [C0201-SMT-TEST]  38.19 54.51 90 top
C298  1u/6.3V_2  [C0201-SMT-TEST]  177.95 24.4 0 top
C299  47u/6.3V_8  [C0805]  159.4 51.69 90 top
C300  100p/25V_2  [C0201-SMT-TEST]  93.07 12.23 0 top
C305  68p/50V_4  [C0402]  181.04 55.78 90 bottom
C306  22u/10V_8  [C0805]  29.78 29.1 0 top
C307  22u/10V_8  [C0805]  29.78 31.13 0 top
C308  22u/10V_8  [C0805]  29.05 39.15 0 top
C309  22u/10V_8  [C0805]  33.87 38.89 180 top
C310  *27p/25V_2  [C0201-SMT-TEST]  100.98 60.08 270 bottom
C313  *27p/25V_2  [C0201-SMT-TEST]  99.21 59.5 0 bottom
C314  *0.1u/16V_2  [C0201-SMT-TEST]  90.32 39.64 0 top
C315  4.7u/6.3V_4  [C0402_2]  55.9 58.86 180 bottom
C316  1u/6.3V_2  [C0201-SMT-TEST]  55.9 59.88 0 bottom
C317  22u/25V_8  [C0805]  70.12 35.24 180 top
C318  47u/6.3V_8  [C0805]  144.23 67.72 270 top
C319  1u/16V_4  [C0402]  52.22 61.91 270 top
C320  0.1u/25V_4  [C0402]  55.14 56.2 180 bottom
C321  22u/25V_8  [C0805]  51.66 51.37 270 top
C322  820p/50V_4  [C0402]  47.59 56.03 90 top
C323  15p/25V_2  [C0201-SMT-TEST]  48.53 56.12 270 top
C324  *0201  [C0201-SMT-TEST]  55.39 55.69 90 top
C325  10u/6.3V_4  [C0402_2]  132.35 79.06 270 top
C326  22u/6.3V_6  [C0603]  138.07 76.77 90 top
C327  10u/6.3V_4  [C0402_2]  133.62 79.06 270 top
C328  22u/6.3V_6  [C0603]  140.2 74.71 0 top
C329  *0201  [C0201-SMT-TEST]  57.8 60.89 0 top
C330  10u/6.3V_4  [C0402_2]  134.89 79.06 270 top
C331  22u/6.3V_6  [C0603]  135.91 77.28 0 top
C332  330p/25V_2  [C0201-SMT-TEST]  48.15 54.47 0 top
C333  *0603  [C0603]  65.93 56.15 90 bottom
C334  10u/6.3V_4  [C0402_2]  118.07 66.45 270 bottom
C335  10u/6.3V_4  [C0402_2]  130.96 79.82 270 top
C336  22u/6.3V_6  [C0603]  140.2 76.19 0 top
C337  47u/6.3V_8  [C0805]  100.57 80.29 270 top
C338  10u/6.3V_4  [C0402_2]  121.12 66.45 270 bottom
C339  47u/6.3V_8  [C0805]  79.52 62.04 90 top
C340  10u/6.3V_4  [C0402_2]  132.35 81.85 90 top
C341  47u/6.3V_8  [C0805]  77.36 62.04 90 top
C342  10u/6.3V_4  [C0402_2]  119.6 66.45 270 bottom
C343  47u/6.3V_8  [C0805]  98.34 80.29 270 top
C344  10u/6.3V_4  [C0402_2]  131.08 81.85 90 top
C345  47u/6.3V_8  [C0805]  96.1 80.29 270 top
C346  10u/6.3V_4  [C0402_2]  123.91 68.23 0 bottom
C347  10u/6.3V_4  [C0402_2]  134.87 78.34 270 bottom
C348  10u/6.3V_4  [C0402_2]  133.62 81.85 90 top
C349  10u/6.3V_4  [C0402_2]  132.68 79.03 180 bottom
C350  47u/6.3V_8  [C0805]  79.93 73.78 315 top
C351  47u/6.3V_8  [C0805]  81.35 75.16 315 top
C352  10u/6.3V_4  [C0402_2]  134.89 81.85 90 top
C353  2.2u/10V_4  [C0402]  72.15 28.47 270 top
C354  4.7u/10V_4  [C0402_2]  38.95 36.6 270 top
C355  10u/6.3V_4  [C0402_2]  123.66 66.83 0 bottom
C356  0.1u/10V_2  [C0201-SMT-TEST]  41.11 36.6 0 top
C357  22u/25V_8  [C0805]  44.93 41.29 90 top
C358  4.7u/10V_4  [C0402_2]  39.31 45.75 270 top
C359  10u/6.3V_4  [C0402_2]  117.44 68.86 180 bottom
C360  22u/25V_8  [C0805]  154.6 80.35 0 top
C361  22u/25V_8  [C0805]  154.59 82.39 0 top
C362  1u/25V_4  [C0402]  160.93 72.96 0 top
C363  1u/10V_4  [C0402]  182.21 44.48 270 top
C364  0.1u/25V_4  [C0402]  160.75 77.43 90 top
C365  22u/10V_8  [C0805]  142.13 81.72 270 top
C366  0.1u/50V_4  [C0402]  177.5 42.68 270 top
C367  22u/10V_8  [C0805]  143.02 73.72 90 top
C368  22u/10V_8  [C0805]  140.1 81.72 270 top
C369  22u/10V_8  [C0805]  144.16 81.24 270 top
C370  *47u/6.3V_8  [C0805]  145.05 54.62 90 top
C371  47u/6.3V_8  [C0805]  146.27 68.25 270 top
C372  1u/25V_4  [C0402]  48.25 61.02 0 top
C373  *47u/6.3V_8  [C0805]  147.08 54.62 90 top
C374  47u/6.3V_8  [C0805]  142 57.04 0 top
C375  *47u/6.3V_8  [C0805]  154.39 67.72 270 top
C376  *47u/6.3V_8  [C0805]  156.43 67.72 270 top
C377  *47u/6.3V_8  [C0805]  158.46 67.72 270 top
C378  220u/2.5V_3528H1.9  [C3528]  137.31 80.71 270 top
C379  *10u/6.3V_6  [C0603]  177.68 39.4 90 top
C380  33p/25V_2  [C0201-SMT-TEST]  183.1 36.98 0 top
C381  220u/2.5V_3528H1.9  [C3528]  168.24 38.13 180 top
C382  22u/6.3V_6  [C0603]  141.75 52.59 270 top
C386  1u/10V_4  [C0402]  182.72 35.33 0 top
C387  22u/6.3V_6  [C0603]  143.27 52.59 270 top
C388  22u/25V_8  [C0805]  174.11 72.25 270 top
C389  22u/25V_8  [C0805]  167.48 73.18 0 top
C390  22u/25V_8  [C0805]  178.15 72.25 270 top
C391  22u/25V_8  [C0805]  176.12 72.25 270 top
C392  22u/25V_8  [C0805]  174.21 65.56 90 top
C393  22u/6.3V_6  [C0603]  139.72 51.98 0 top
C394  22u/25V_8  [C0805]  176.24 65.56 90 top
C395  22u/25V_8  [C0805]  45.71 51.37 270 top
C396  22u/25V_8  [C0805]  47.69 51.37 270 top
C397  22u/25V_8  [C0805]  49.68 51.37 270 top
C398  22u/25V_8  [C0805]  173.05 37.24 0 top
C399  22u/25V_8  [C0805]  70.68 27.64 270 top
C400  22u/25V_8  [C0805]  45.66 33.25 90 top
C401  22u/10V_8  [C0805]  76.56 35.46 270 top
C402  22u/10V_8  [C0805]  29.05 45.24 0 top
C403  0.1u/25V_4  [C0402]  179.92 61.49 90 top
C404  0.1u/25V_4  [C0402]  179.39 57.91 90 top
C405  330p/50V_4  [C0402]  182.33 58.45 0 bottom
C406  0.1u/50V_4  [C0402]  66.19 31.68 270 top
C407  GS@4.7u/10V_4  [C0402_2]  188.23 79.4 0 bottom
C412  0.1u/6.3V_2  [C0201-SMT-TEST]  116.34 57.3 180 bottom
C413  4.7u/10V_4  [C0402_2]  118.83 57.3 0 bottom
C414  10u/6.3V_4  [C0402_2]  128.64 57.19 0 bottom
C416  0.1u/6.3V_2  [C0201-SMT-TEST]  112.05 58.83 180 bottom
C418  *0.1u/6.3V_2  [C0201-SMT-TEST]  124.04 59.21 90 bottom
C419  *4.7u/10V_4  [C0402_2]  122.77 59.21 270 bottom
C422  *0.1u/6.3V_2  [C0201-SMT-TEST]  127.17 58.42 0 bottom
C424  *10u/6.3V_4  [C0402_2]  124.1 57.59 270 bottom
C426  *4.7u/10V_4  [C0402_2]  120.74 58.83 0 bottom
C474  1u/10V_2  [C0201-SMT-TEST]  107.66 56.54 180 bottom
C486  0.1u/16V_2  [C0201-SMT-TEST]  103.49 50.83 90 bottom
C487  1u/10V_2  [C0201-SMT-TEST]  102.73 50.83 270 bottom
C488  *1u/10V_2  [C0201-SMT-TEST]  108.22 63.05 0 bottom
C489  4.7u/10V_4  [C0402_2]  100.09 52.36 45 bottom
C491  2.2u/10V_4  [C0402]  101.16 51.19 90 bottom
C502  8.2p/50V_4  [C0402]  138.39 64.03 90 bottom
C503  8.2p/50V_4  [C0402]  135.09 69.11 270 bottom
C504  8.2p/50V_4  [C0402]  131.41 66.45 0 bottom
C583  47u/6.3V_8  [C0805]  142 54.93 0 top
C587  *22u/6.3V_6  [C0603]  139.36 68.64 270 top
C1000  *1u/10V_4  [C0402]  188.05 36.35 90 top
C1001  0.033u/6.3V_2  [C0201-SMT-TEST]  182.08 37.54 180 top
C1002  0.1u/6.3V_2  [C0201-SMT-TEST]  30.55 65.28 0 bottom
C1003  0.1u/6.3V_2  [C0201-SMT-TEST]  32.92 62.38 180 bottom
C1004  0.1u/6.3V_2  [C0201-SMT-TEST]  30.55 62.38 0 bottom
C1005  0.1u/6.3V_2  [C0201-SMT-TEST]  30.55 63.68 0 bottom
C1006  0.1u/6.3V_2  [C0201-SMT-TEST]  32.92 64.76 180 bottom
C1007  4700p/50V_4  [C0402]  55.77 12.98 270 bottom
C1008  *0.1u/25V_4  [C0402]  57.17 14.16 0 bottom
C1009  4700p/50V_4  [C0402]  55.77 11.2 90 bottom
C1010  *0.1u/25V_4  [C0402]  57.17 11.11 0 bottom
C1011  4.7u/6.3V_4  [C0402_2]  66.55 18.31 180 top
C1012  2.2u/10V_4  [C0402]  62.18 22.5 0 bottom
C1013  0.068u/50V_6  [C0603]  63.24 18.07 270 bottom
C1014  *0.068u/50V_6  [C0603]  61.77 18.07 270 bottom
C1015  *0.033u/25V_4  [C0402]  59.15 15.68 90 bottom
C1016  1u/25V_4  [C0402]  47.81 39.01 0 top
C1017  0.033u/25V_4  [C0402]  59.15 17.46 270 bottom
C1018  1u/25V_4  [C0402]  47.81 38.05 0 top
C1025  *0.1u/6.3V_2  [C0201-SMT-TEST]  147.86 16.71 270 top
C1027  0.1u/6.3V_2  [C0201-SMT-TEST]  149.19 17.33 180 top
C1028  0.1u/25V_2  [C0201-SMT-TEST]  61.74 20.71 0 bottom
C1035  *0.1u/25V_4  [C0402]  68.37 15.78 270 top
C1036  22u/25V_8  [C0805]  49.12 8.63 0 top
C1045  GMR@0.1u/16V_4  [C0402]  15.51 67.54 270 top
C3205  22u/6.3V_6  [C0603]  139.66 63.91 90 bottom
C3208  22u/6.3V_6  [C0603]  141.31 63.78 90 top
C3210  22u/6.3V_6  [C0603]  141.82 61.75 0 top
C3213  22u/6.3V_6  [C0603]  139.79 63.78 90 top
C3216  22u/6.3V_6  [C0603]  141.19 63.91 90 bottom
C3406  10u/6.3V_4  [C0402_2]  117.24 80.07 180 top
C3423  1u/10V_2  [C0201-SMT-TEST]  116.6 78.8 180 top
C3501  47u/6.3V_6  [C0603]  112.03 62.42 90 bottom
C3504  47u/6.3V_6  [C0603]  119.78 62.42 90 bottom
C3508  47u/6.3V_6  [C0603]  118.26 62.42 90 bottom
C3512  47u/6.3V_6  [C0603]  116.73 62.42 90 bottom
C3514  47u/6.3V_6  [C0603]  115.21 62.42 90 bottom
C3517  47u/6.3V_6  [C0603]  113.56 62.42 90 bottom
C3522  10u/6.3V_4  [C0402_2]  101.39 74.74 180 bottom
C3526  10u/6.3V_4  [C0402_2]  98.01 75.97 270 bottom
C3530  10u/6.3V_4  [C0402_2]  99.28 75.97 270 bottom
C3531  10u/6.3V_4  [C0402_2]  96.61 75.97 270 bottom
C3535  47u/6.3V_6  [C0603]  121.3 62.42 90 bottom
C3562  *12p/50V_4  [C0402]  94.5 76.63 90 bottom
C3563  *12p/50V_4  [C0402]  95.52 76.63 90 bottom
C3564  *12p/50V_4  [C0402]  93.48 76.63 90 bottom
C3609  47u/6.3V_6  [C0603]  91.99 74.13 90 top
C4101  12p/50V_2  [C0201-SMT-TEST]  114.52 78.69 0 top
C4102  12p/50V_2  [C0201-SMT-TEST]  113.5 78.69 180 top
C4103  15p/50V_2  [C0201-SMT-TEST]  94.32 49.68 0 top
C4104  15p/50V_2  [C0201-SMT-TEST]  92.29 49.68 180 top
C4301  *0.1u/16V_2  [C0201-SMT-TEST]  155.54 36.58 0 top
C4401  *0.1u/16V_2  [C0201-SMT-TEST]  133.22 25.82 0 top
C4501  1u/10V_2  [C0201-SMT-TEST]  138.77 30.63 90 bottom
C4502  1u/10V_2  [C0201-SMT-TEST]  145.89 36.58 180 top
C4503  10u/10V_6  [C0603]  148.04 35.97 0 top
C4504  1u/10V_2  [C0201-SMT-TEST]  130.26 31.4 90 bottom
C4505  1u/10V_2  [C0201-SMT-TEST]  157.19 36.58 0 top
C4506  1u/10V_2  [C0201-SMT-TEST]  138.77 38.51 90 bottom
C4507  10u/10V_6  [C0603]  127.3 30.54 90 top
C4508  1u/10V_2  [C0201-SMT-TEST]  146.77 48.31 0 top
C4509  1u/10V_2  [C0201-SMT-TEST]  127.72 38.38 90 bottom
C4510  1u/10V_2  [C0201-SMT-TEST]  130.96 42.66 0 top
C4511  1u/10V_2  [C0201-SMT-TEST]  148.04 36.98 180 bottom
C4512  *1u/10V_2  [C0201-SMT-TEST]  159.88 39.52 270 top
C4513  *1u/10V_2  [C0201-SMT-TEST]  159.89 45.35 270 top
C4514  1u/10V_2  [C0201-SMT-TEST]  147.28 47.91 180 bottom
C4515  1u/10V_2  [C0201-SMT-TEST]  155.16 47.91 180 bottom
C4516  1u/10V_2  [C0201-SMT-TEST]  155.54 40.03 0 bottom
C4517  1u/10V_2  [C0201-SMT-TEST]  127.44 28.6 90 top
C4518  1u/10V_2  [C0201-SMT-TEST]  130.7 25.92 0 top
C4519  1u/10V_2  [C0201-SMT-TEST]  136.04 25.92 180 top
C4520  1u/10V_2  [C0201-SMT-TEST]  136.87 42.67 180 top
C4521  *1u/10V_2  [C0201-SMT-TEST]  143.12 39.27 270 top
C4522  *1u/10V_2  [C0201-SMT-TEST]  139.18 29.74 90 top
C4523  10u/10V_6  [C0603]  152.75 35.49 180 top
C4524  10u/10V_6  [C0603]  137.76 44.51 180 top
C4525  1u/10V_2  [C0201-SMT-TEST]  127.65 36.76 90 top
C4526  *10u/10V_6  [C0603]  140.25 34.95 90 top
C4527  1u/10V_2  [C0201-SMT-TEST]  127.65 35.49 90 top
C4528  *10u/10V_6  [C0603]  101.34 40.96 180 top
C4529  1u/10V_2  [C0201-SMT-TEST]  127.42 32.4 270 top
C4530  1u/10V_2  [C0201-SMT-TEST]  139.18 36.6 270 top
C4531  10u/10V_6  [C0603]  142.71 37.36 90 top
C4532  10u/10V_6  [C0603]  140.25 30.38 270 top
C4533  *10u/10V_6  [C0603]  157.44 35.51 180 top
C4534  1u/10V_2  [C0201-SMT-TEST]  139.18 32.54 270 top
C4535  1u/10V_2  [C0201-SMT-TEST]  139.18 31.27 270 top
C4536  1u/10V_2  [C0201-SMT-TEST]  153.12 48.31 0 top
C4537  1u/10V_2  [C0201-SMT-TEST]  160.04 42.58 0 top
C4538  1u/10V_2  [C0201-SMT-TEST]  149.44 48.31 0 top
C4539  1u/10V_2  [C0201-SMT-TEST]  143.12 44.6 90 top
C4540  1u/10V_2  [C0201-SMT-TEST]  151.35 36.58 180 top
C4541  1u/10V_2  [C0201-SMT-TEST]  152.62 36.58 180 top
C4601  *0.1u/16V_2  [C0201-SMT-TEST]  119.22 25.91 0 top
C4701  *0.1u/16V_2  [C0201-SMT-TEST]  89.75 31.52 180 top
C4801  1u/10V_2  [C0201-SMT-TEST]  96.86 29.62 90 bottom
C4802  1u/10V_2  [C0201-SMT-TEST]  92.37 37.35 270 top
C4803  1u/10V_2  [C0201-SMT-TEST]  115.46 37.53 270 bottom
C4804  1u/10V_2  [C0201-SMT-TEST]  125.44 29.49 90 top
C4805  1u/10V_2  [C0201-SMT-TEST]  103.98 30 90 bottom
C4806  1u/10V_2  [C0201-SMT-TEST]  122.26 25.91 0 top
C4807  1u/10V_2  [C0201-SMT-TEST]  97.52 35.46 270 bottom
C4808  1u/10V_2  [C0201-SMT-TEST]  122.19 42.68 180 top
C4809  10u/10V_6  [C0603]  97.5 40.95 180 top
C4810  *1u/10V_2  [C0201-SMT-TEST]  113.88 29.36 90 top
C4811  1u/10V_2  [C0201-SMT-TEST]  103.98 39.27 270 bottom
C4812  *1u/10V_2  [C0201-SMT-TEST]  106.52 40.59 0 top
C4813  10u/10V_6  [C0603]  112.87 30.63 0 top
C4814  1u/10V_2  [C0201-SMT-TEST]  125.31 38.38 90 bottom
C4815  1u/10V_2  [C0201-SMT-TEST]  114.26 30.25 270 bottom
C4816  1u/10V_2  [C0201-SMT-TEST]  125.18 30.51 90 bottom
C4817  1u/10V_2  [C0201-SMT-TEST]  116.42 42.63 0 top
C4818  1u/10V_2  [C0201-SMT-TEST]  104.18 40.6 180 top
C4819  1u/10V_2  [C0201-SMT-TEST]  105.5 28.83 180 top
C4820  1u/10V_2  [C0201-SMT-TEST]  95.34 28.83 180 top
C4821  *1u/10V_2  [C0201-SMT-TEST]  95.14 40.57 180 top
C4822  1u/10V_2  [C0201-SMT-TEST]  98.9 28.83 0 top
C4823  *1u/10V_2  [C0201-SMT-TEST]  92.37 32.03 90 top
C4824  10u/10V_6  [C0603]  112.81 33.33 90 top
C4825  1u/10V_2  [C0201-SMT-TEST]  99.56 40.73 270 top
C4826  10u/10V_6  [C0603]  112.81 35.99 270 top
C4827  1u/10V_2  [C0201-SMT-TEST]  103.17 40.6 0 top
C4828  *10u/10V_6  [C0603]  140.25 37.62 270 top
C4829  1u/10V_2  [C0201-SMT-TEST]  109.94 32.41 270 top
C4830  *10u/10V_6  [C0603]  92.01 34.7 90 top
C4831  10u/10V_6  [C0603]  105.63 27.33 0 top
C4832  10u/10V_6  [C0603]  126.45 26.19 90 top
C4833  *10u/10V_6  [C0603]  96.23 27.33 0 top
C4834  1u/10V_2  [C0201-SMT-TEST]  99.91 28.83 180 top
C4835  1u/10V_2  [C0201-SMT-TEST]  102.83 28.83 180 top
C4836  1u/10V_2  [C0201-SMT-TEST]  113.88 36.73 90 top
C4837  1u/10V_2  [C0201-SMT-TEST]  113.88 33.81 270 top
C4838  1u/10V_2  [C0201-SMT-TEST]  113.88 31.9 270 top
C4839  1u/10V_2  [C0201-SMT-TEST]  125.44 36.38 270 top
C4840  1u/10V_2  [C0201-SMT-TEST]  125.44 33.56 270 top
C4841  1u/10V_2  [C0201-SMT-TEST]  125.44 31.27 270 top
C10711  0.1u/16V_4  [C0402]  98.44 23.25 0 top
C27101  0.01u/25V_2  [C0201-SMT-TEST]  182.46 49.18 90 top
C27102  *2200p/50V_4  [C0402]  177.69 55.94 270 bottom
C27104  4.7u/10V_4  [C0402_2]  183.6 50.95 90 top
C27218  47u/6.3V_8  [C0805]  157.37 51.69 90 top
C27220  47u/6.3V_8  [C0805]  148.3 68.25 270 top
C27222  22u/25V_8  [C0805]  167.4 68.9 0 top
C27224  22u/25V_8  [C0805]  172.1 72.25 270 top
C27226  22u/25V_8  [C0805]  167.48 71.15 0 top
C27228  22u/25V_8  [C0805]  178.27 65.56 90 top
C27230  3300p/50V_6  [C0603]  162.22 50.6 90 top
C28002  0.1u/50V_4  [C0402]  62.86 35.73 90 bottom
C28003  *0.01u/25V_4  [C0402]  61.87 35.73 270 bottom
C28004  GS@0.1u/6.3V_2  [C0201-SMT-TEST]  188.49 80.41 180 bottom
C28005  *220u/2.5V_3528H1.9  [C3528]  74.19 53.86 90 top
C28006  0.1u/6.3V_2  [C0201-SMT-TEST]  32.92 63.55 180 bottom
C28007  10u/10V_4  [C0402_2]  42.51 12.06 0 top
C28008  0.1u/16V_2  [C0201-SMT-TEST]  42.52 10.07 0 top
C28009  0.01u/16V_4  [C0402]  42.51 10.97 0 top
C28010  0.1u/6.3V_2  [C0201-SMT-TEST]  41.04 59.88 270 bottom
C28011  0.1u/6.3V_2  [C0201-SMT-TEST]  46.63 64.32 180 top
C28015  0.1u/16V_2  [C0201-SMT-TEST]  163.72 30.54 270 bottom
C28016  0.1u/16V_2  [C0201-SMT-TEST]  171.1 28.79 180 bottom
C28017  1000p/25V_2  [C0201-SMT-TEST]  24.28 26.48 180 bottom
C28018  1000p/25V_2  [C0201-SMT-TEST]  27.05 26.52 0 bottom
C28019  1000p/25V_2  [C0201-SMT-TEST]  27.3 25.73 180 bottom
C28020  1000p/25V_2  [C0201-SMT-TEST]  29.97 25.83 0 bottom
C28021  *0.1u/25V_4  [C0402]  186.53 49.34 180 bottom
C28022  22u/6.3V_6  [C0603]  92.86 23.23 180 bottom
C28023  *22u/6.3V_6  [C0603]  90.8 23.43 270 bottom
C28024  KBL@4.7u/25V_6  [C0603]  69.89 13.08 0 top
C28025  KBL@2.2u/25V_4  [C0402]  75.33 14.88 180 top
C28026  KBL@1u/25V_4  [C0402]  76.94 14.31 270 top
CN2  KBL@50505-00401-V01  [50505-00401-V01-4P-L]  75.6 14.55 180 bottom
CR1  MESD11LH5.0CT5G  [R0201-SMT-TEST]  14.75 28.56 270 top
CR2  MESD11LH5.0CT5G  [R0201-SMT-TEST]  14.75 27.57 90 top
CR3  MESD11LH5.0CT5G  [R0201-SMT-TEST]  14.75 25.03 270 top
CR4  MESD11LH5.0CT5G  [R0201-SMT-TEST]  14.75 24.02 270 top
CR5  MESD11LH5.0CT5G  [R0201-SMT-TEST]  14.75 23 270 top
CR6  MESD11LH5.0CT5G  [R0201-SMT-TEST]  14.75 29.55 270 top
CR7  MESD11LH5.0CT5G  [R0201-SMT-TEST]  14.75 30.54 270 top
D1  *TPD4E101DPWR  [SON4-0_8X0_8-48-5P-0_4H]  132 20.03 180 top
D2  *TPD4E101DPWR  [SON4-0_8X0_8-48-5P-0_4H]  135.81 20.03 180 top
D3  *TPD4E101DPWR  [SON4-0_8X0_8-48-5P-0_4H]  139.73 20.08 180 top
D4  *TPD4E101DPWR  [SON4-0_8X0_8-48-5P-0_4H]  142.51 20.08 180 top
D5  PUSB3FR4  [ESD10-2_5X1-5-0_5H]  15.26 54.8 270 top
D7  PUSB3FR4  [ESD10-2_5X1-5-0_5H]  13.21 70.79 90 top
D8  PUSB3FR4  [ESD10-2_5X1-5-0_5H]  11.19 67.4 225 bottom
D9  BAT54CT-7-F  [SOT23-1_38-5-3P]  179.74 25.55 270 bottom
D10  SDM03U40-7  [D-1_2X0_8-0_7H]  165.58 26.43 180 top
D11  PESD5V0V1BDSF  [D-0_6X0_3-0_32H-SMT]  15.77 47.31 90 top
D12  PESD5V0V1BDSF  [D-0_6X0_3-0_32H-SMT]  12.72 34.48 270 bottom
D13  PESD5V0V1BDSF  [D-0_6X0_3-0_32H-SMT]  21.75 46.46 90 top
D14  PESD5V0V1BDSF  [D-0_6X0_3-0_32H-SMT]  14.75 47.31 90 top
D15  PESD5V0V1BDSF  [D-0_6X0_3-0_32H-SMT]  19.32 47.31 90 top
D16  *TPD4E101DPWR  [SON4-0_8X0_8-48-5P-0_4H]  126.47 19.94 180 top
D17  *TPD4E101DPWR  [SON4-0_8X0_8-48-5P-0_4H]  128.64 19.98 180 top
D18  RB751V-40  [D-SOD323-1_85X1_25-0_95H]  185.71 37.59 180 top
D19  RB751S40  [D-1_2X0_8-0_65H]  81.32 13.74 0 top
D20  SDM03U40-7  [D-1_2X0_8-0_7H]  167.02 31.38 0 top
D21  SDM03U40-7  [D-1_2X0_8-0_7H]  172.95 21.58 180 top
D22  RB521CS30L  [D-1X0_6-0_53H]  88.35 42.83 0 bottom
D23  SDM03U40-7  [D-1_2X0_8-0_7H]  52.22 58.86 90 bottom
D24  RB521S30FN2  [D-1X0_6-2P-PJE24VM5FN2]  85.29 13.93 90 top
D25  PJE24VM5FN2  [D-1X0_6-2P-PJE24VM5FN2]  9.09 74.97 0 top
D26  *BAT54CLT1G  [SOT23-2-95-3P]  56.05 38.03 270 bottom
D27  *RB751V-40  [D-SOD323-1_85X1_25-0_95H]  51.45 68.9 0 top
D28  RB751S40  [D-1_2X0_8-0_65H]  86.21 12.36 180 top
D29  RB751S40  [D-1_2X0_8-0_65H]  81.67 12.33 0 top
D30  RB751S40  [D-1_2X0_8-0_65H]  82.06 15.43 0 top
D31  *RB751S40  [D-1_2X0_8-0_7H]  72.28 69.78 180 top
D32  SDM03U40-7  [D-1_2X0_8-0_7H]  90.32 69.35 90 top
D33  SDM03U40-7  [D-1_2X0_8-0_7H]  88.86 46 270 top
D34  SDM03U40-7  [D-1_2X0_8-0_7H]  90.39 46 270 top
D35  RB521CS30L  [D-1X0_6-0_53H]  65.93 68.01 0 top
D36  RB751V-40  [D-SOD323-1_85X1_25-0_95H]  53.36 37.91 270 bottom
D38  SDM03U40-7  [D-1_2X0_8-0_7H]  90.61 44.27 180 bottom
D39  *RB751V-40  [D-SOD323-1_85X1_25-0_95H]  174.33 59.97 270 top
D40  RB751V-40  [D-SOD323-1_85X1_25-0_95H]  166.64 77.4 0 top
D1000  *RB751V-40  [D-SOD323-1_85X1_25-0_95H]  187.8 39.46 180 top
D1001  SDM03U40-7  [D-1_2X0_8-0_7H]  149.37 26.81 180 bottom
D2741  PESD5V0X2UM  [D3-1X0_6-3P]  9.05 73.72 180 top
D2742  PESD5V0X2UM  [D3-1X0_6-3P]  15.92 57.86 180 top
D2743  GMR@ESD5451N-2/TR  [R0402]  14.65 65.81 180 top
D2744  RB751V-40  [D-SOD323-1_85X1_25-0_95H]  95.93 23.46 0 bottom
D2745  PJE24VM5FN2  [D-1X0_6-2P-PJE24VM5FN2]  33.42 67.08 270 bottom
D2746  PJE24VM5FN2  [D-1X0_6-2P-PJE24VM5FN2]  33.42 69.02 90 bottom
D2747  KBL@SBR2A40P1-7  [D-SOD123-2_8X1_78]  70.4 9.98 270 top
D2748  GMR@ESD5451N-2/TR  [R0402]  13.04 68.03 270 top
DS1  19-337C/RSBHGHC-A01/2T  [LED19-337C-RSBHGHC-M01-2T-6P]  4.15 12 90 top
F1  LP-MSM150/24  [F4_55X3_24-5_23-1_8H]  43.45 61.78 90 top
FB1  BLM03AX241SN1D  [FILTER-BLM03HG601SN1D-SMT]  151.78 17.42 270 top
HOLE1  *2D-BARCODE-8X8-S  [2D-BARCODE-8X8-S]  80.43 32.5 270 bottom
HOLE2  *2D-BARCODE-8X8-S  [2D-BARCODE-8X8-S]  189.06 72.79 90 top
HOLE17  *H-TC354IC244BC276D244P2  [H-TC354IC244BC276D244P2]  25.05 51.35 180 bottom
HOLE18  *h-tc354ibc276d118p2  [H-TC354IBC276D118P2]  81.7 85.4 180 bottom
HOLE19  *h-c276i158d118p2  [H-C276I158D118P2]  89.19 62.1 180 bottom
HOLE20  *h-c276i158d118p2  [H-C276I158D118P2]  148.12 62.1 180 bottom
HOLE21  *H-C157D157N  [H-C157D157N]  151.18 53.7 180 bottom
HOLE22  *H-C157D157N  [H-C157D157N]  85.48 52.5 180 bottom
HOLE23  *h-c150d118p2  [H-C150D118P2]  192.2 13.1 180 bottom
HOLE25  *h-tc315ibc276d118p2  [H-TC315IBC276D118P2]  184.7 85.4 180 bottom
HOLE26  *h-tc354ibc276d118p2  [H-TC354IBC276D118P2]  184.2 13.1 180 bottom
HOLE27  *H-TC315IC118BC276D118P2  [H-TC315IC118BC276D118P2]  63.7 9.1 180 bottom
HOLE28  *h-tc354ibc276d118p2  [H-TC354IBC276D118P2]  14.1 12.15 180 bottom
HOLE29  *h-c256d118p2  [H-C256D118P2]  21.4 68.9 0 top
HOLE32  *SPAD-C276NP  [SPAD-C276NP]  194.63 55.35 0 top
HOLE34  *spad-re213x866np  [SPAD-RE213X866NP]  195.5 34.4 0 top
HOLE35  *SPAD-RE1140X157NP  [SPAD-RE1140X157NP]  124.2 11.6 0 top
HOLE36  *spad-re669x157np  [SPAD-RE669X157NP]  38.2 7.61 0 top
HOLE38  *h-c142d118p2  [H-C142D118P2]  89.35 85.4 0 top
HOLE39  *h-o154x142d130x118p2  [H-O154X142D130X118P2]  177.21 85.4 0 top
HOLE40  *SPAD-RE591X110NP  [SPAD-RE591X110NP]  122.2 88 180 bottom
HOLE41  *spad-re517x99np  [SPAD-RE517X99NP]  6.57 80.41 180 bottom
HOLE42  *SPAD-RE130X299NP  [SPAD-RE130X299NP]  1.65 73.86 180 bottom
HOLE43  *SPAD-RE591X130NP  [SPAD-RE591X130NP]  122.2 87.75 0 top
HOLE44  *spad-re236x197np  [SPAD-RE236X197NP]  112.7 12.1 180 bottom
HOLE45  *spad-zac-1np  [SPAD-ZAC-1NP]  2.75 26.1 180 bottom
HOLE46  *spad-zac-2np  [SPAD-ZAC-2NP]  3.4 9.2 180 bottom
J1  *18-6056-01  [18-6056-01-2P-L]  186.64 22.66 0 bottom
J2  *18-6056-01  [18-6056-01-2P-L]  173.6 13.8 0 bottom
J3  *P-PHM-08127S-G6  [P-PHM-08127S-G6-8P-LDV]  184.94 30.11 180 bottom
J4  50278-00401-V01  [WTB-50278-00401-V01-4P-L]  26.7 17.72 180 bottom
J9  5-251907001000-6  [SDCARD-5-251907001000-6-9P-R]  6.15 25.85 270 top
J10  30154-00902-V01  [UB3-30154-00902-V01-9P]  4.6 56.8 270 top
J11  UT11113-1220Q-7H  [UB31-UT11113-1220Q-7H-24P]  5.4 73.85 270 top
J12  50696-0200M-V02  [50696-0200M-V02-20P-L]  195.67 55.4 270 bottom
J13  196650-50041-3  [FPC-196650-50041-3-50P-L]  195.93 34.4 270 bottom
J14  50458-00801-V02  [WTB-50458-00801-V02-8P-L]  97.6 12.72 180 bottom
J15  *QSH-030-01-L-D-A-K-TR  [BTB-QSH-030-01-L-D-A-K-TR-60P-RUV]  81.81 68.51 230.5 bottom
J16  2SJ3080-123111F  [PHJK-2SJ3080-123111F-6P]  4.29 41.2 270 top
J17  51643-0300N-V01  [FPC-51643-0300N-V01-30P-L]  133.98 19.05 180 bottom
J18  50506-00601-V01  [FPC-50506-00601-V01-6P-L]  160.9 19.75 180 bottom
J23  196522-40041-3  [51693-04001-V01-40P-L]  51.5 67.25 0 bottom
J24  GS@50208-00601-V02  [50208-00601-V02-6P-L]  192.95 80.1 270 bottom
J25  *51646-0300N-V01  [FPC-51646-0300N-V01-30P-L]  132.27 15.5 180 bottom
L1  NFP0QHB542HS2D  [FILTER-NFP0QHB542HS2D-4P-SMT]  12.83 66.8 225 bottom
L2  NFP0QHB542HS2D  [FILTER-NFP0QHB542HS2D-4P-SMT]  14.79 71.55 90 top
L3  NFP0QHB542HS2D  [FILTER-NFP0QHB542HS2D-4P-SMT]  14.83 69.96 90 top
L4  NFP0QHB542HS2D  [FILTER-NFP0QHB542HS2D-4P-SMT]  11.89 65.64 225 bottom
L5  NFP0QHB542HS2D  [FILTER-NFP0QHB542HS2D-4P-SMT]  10.81 71.75 0 top
L6  NFP0QHB542HS2D  [FILTER-NFP0QHB542HS2D-4P-SMT]  17.57 57.86 90 top
L7  NFP0QHB542HS2D  [FILTER-NFP0QHB542HS2D-4P-SMT]  16.91 54.04 90 top
L8  NFP0QHB542HS2D  [FILTER-NFP0QHB542HS2D-4P-SMT]  16.91 55.56 90 top
L9  2.2uH_7.3x6.8x2.0  [L6_6X6_6-1_8H]  50.31 23.43 90 top
L10  1uH_2.5x2.0x1.2  [L2_5X2-1_2]  64 32.87 0 top
L11  10uH_4x4x1.8  [L4X4-1_8]  65.68 36.43 0 top
L12  0.15uH_7.6x6.8x2.4  [L6_6X6_6-2_2H]  66.82 56.32 0 top
L13  1.0uH_5x5x1.8  [L5_1X5_2-1_6H]  149.62 75.25 180 top
L14  1.0uH_5x5x1.8  [L5_1X5_2-1_6H]  167.86 42.7 180 top
L15  1.0uH_5x5x1.8  [L5_1X5_2-1_6H]  34.02 42.83 180 top
L16  1.0uH_5x5x1.8  [L5_1X5_2-1_6H]  34.71 32.79 180 top
L17  1.5uH_5x5x1.8  [L5_1X5_2-1_6H]  78.25 30.03 90 top
L3601  *0.47uH_2.0X1.6X1  [L2X1_6-1_6-1H]  93.92 73.95 90 top
L27202  0.22uH_11.5x10.3x2.0  [L10_3X10-4H-SMT]  160.29 60.62 180 top
L27203  KBL@10uH_4x4x1.2  [CHOKE-PHI014B-1R0MS]  73.81 9.83 270 top
NOREF  -  []  11.27 -59.79 0 top
NOREF#2  -  [unnamed#2]  191.27 86.22 0 top
NOREF#3  -  [unnamed#2]  72.01 50.19 0 top
NOREF#4  -  []  100.53 13.01 0 top
NOREF#5  -  [unnamed#2]  70.88 39.14 90 top
NOREF#6  -  []  183.08 -38.42 0 top
NOREF#7  -  [unnamed#2]  193.44 18.86 0 top
NOREF#8  -  [unnamed#2]  8.4 10.73 0 top
NOREF#9  -  [unnamed#2]  162.95 18.92 180 top
NOREF#10  -  [unnamed#2]  60.41 43.66 0 top
NOREF#11  -  [unnamed#2]  163.49 18.54 90 top
NOREF#12  -  [unnamed#2]  195.1 86.21 180 bottom
NOREF#13  -  []  166.01 64.75 180 bottom
NOREF#14  -  [unnamed#2]  6.75 7.83 180 bottom
NOREF#15  -  [unnamed#2]  194.96 17.08 180 bottom
Q2  AONR32314  [DFN-8L-3X3-65-5P-0_9H]  86.63 19.67 270 bottom
Q3  SIRA06DP-T1-GE3  [POWER-5_89X4_9-1_27-5P]  171.14 54.22 270 top
Q4  DMG1012T-7  [SOT23-1_38-5-3P]  166.77 29.48 180 top
Q5  DMG1012T-7  [SOT23-1_38-5-3P]  175.11 18.43 180 bottom
Q6  AO3413  [SOT23-2_38-95-3P]  181.46 22.96 270 bottom
Q9  DMG1012T-7  [SOT23-1_38-5-3P]  161.25 69.11 270 top
Q10  DMG1012T-7  [SOT23-1_38-5-3P]  163.72 68.91 270 top
Q12  DMG1012T-7  [SOT23-1_38-5-3P]  31.4 69.76 90 top
Q13  DMG1012T-7  [SOT23-1_38-5-3P]  29.04 69.76 90 top
Q14  2N7002K  [SOT23-2-95-3P]  94.63 20.84 90 bottom
Q15  DMG1012T-7  [SOT23-1_38-5-3P]  172.52 23.39 180 top
Q16  BSS84AKM  [D3-1X0_6-3P]  86.87 15.84 270 top
Q17  DMG1012T-7  [SOT23-1_38-5-3P]  88.77 12.84 0 top
Q18  PMZB670UPE  [D3-1X0_6-3P]  86.89 13.9 90 top
Q19  DMG1012T-7  [SOT23-1_38-5-3P]  91.31 12.94 0 top
Q20  DMG1012T-7  [SOT23-1_38-5-3P]  85.69 40.54 180 top
Q21  *DMG1012T-7  [SOT23-1_38-5-3P]  85.69 42.83 180 top
Q22  DMG1012T-7  [SOT23-1_38-5-3P]  160.7 17.79 180 top
Q23  BSS84AKM  [D3-1X0_6-3P]  153.94 16.19 270 top
Q24  DMG1012T-7  [SOT23-1_38-5-3P]  62.7 66.7 90 top
Q25  *DMG1012T-7  [SOT23-1_38-5-3P]  60.41 66.7 90 top
Q26  DMG1012T-7  [SOT23-1_38-5-3P]  55.9 66.7 90 top
Q27  DMG1012T-7  [SOT23-1_38-5-3P]  58.18 66.7 90 top
Q28  BSS84AKM  [D3-1X0_6-3P]  64.41 65.47 90 top
Q30  SIRA10DP-T1-GE3  [POWER-5_89X4_9-1_27-5P]  170.27 61.75 270 top
Q31  SIRA06DP-T1-GE3  [POWER-5_89X4_9-1_27-5P]  165.62 51.51 270 top
Q32  SIRA10DP-T1-GE3  [POWER-5_89X4_9-1_27-5P]  57.3 49.21 90 top
Q33  SIRA10DP-T1-GE3  [POWER-5_89X4_9-1_27-5P]  59.45 56.7 90 top
Q34  AON6996  [POWER-5_2X5_55-1_27-7P-1H]  174.08 42.27 0 top
Q35  AON6996  [POWER-5_2X5_55-1_27-7P-1H]  157.06 76.02 180 top
Q36  DMG1012T-7  [SOT23-1_38-5-3P]  187.38 41.82 0 top
Q37  DMG1012T-7  [SOT23-1_38-5-3P]  185.89 44.48 0 top
Q38  PJE138K  [SOT23-1_38-5-3P]  27.8 57.43 0 top
Q1000  AONR32314  [DFN-8L-3X3-65-5P-0_9H]  49.79 11.58 0 top
Q1001  AON6998  [POWER-5X6-1_27-7P-0_8H]  51.33 16.19 90 top
Q1002  DMG1012T-7  [SOT23-1_38-5-3P]  46.25 68.64 0 top
Q1008  AON6998  [POWER-5X6-1_27-7P-0_8H]  56.61 27.04 180 top
Q1009  PMZ370UNE  [D3-1X0_6-3P]  56.15 20 90 bottom
Q1010  DMG1012T-7  [SOT23-1_38-5-3P]  48.79 67.12 0 top
R1  GMR@1K_5%_4  [R0402]  13.04 66.23 270 top
R1G1  *4.7K_1%_2  [R0201-SMT-TEST]  94.96 66.47 270 top
R1G3  100K_1%_2  [R0201-SMT-TEST]  94.2 66.47 90 top
R1H18  *2.2K_1%_2  [R0201-SMT-TEST]  96.28 65.42 0 top
R2  *2.2K_5%_2  [R0201-SMT-TEST]  94.89 64.91 90 bottom
R2C20  10K_1%_2  [R0201-SMT-TEST]  91.76 42.7 90 top
R2F1  43_5%_4  [R0402]  179.29 49.3 270 top
R2F3  *Short_0402  [S0402]  125.95 80.99 270 top
R2F14  *Short_0402  [S0402]  123.84 80.99 270 top
R3  *100K_1%_2  [R0201-SMT-TEST]  73.81 70.55 315 bottom
R3C14  *4.7K_1%_2  [R0201-SMT-TEST]  94.73 60.92 0 top
R3C18  *1M_1%_2  [R0201-SMT-TEST]  91.02 42.7 270 top
